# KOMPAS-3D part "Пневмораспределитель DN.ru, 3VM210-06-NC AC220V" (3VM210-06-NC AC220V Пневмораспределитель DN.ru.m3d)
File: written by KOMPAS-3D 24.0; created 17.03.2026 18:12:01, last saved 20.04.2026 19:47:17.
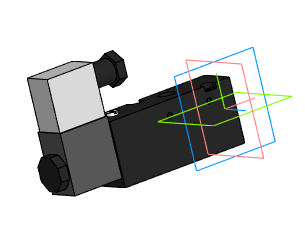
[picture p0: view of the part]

Document properties: Автор: R2D2; Полное имя файла: ..\AC24V\3VM210-06-NC AC24V Пневмораспредели тель DN.ru.cdw

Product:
- Part/product: Пневмораспределитель DN.ru  | designation 3VM210-06-NC AC220V
    Масса: 0.3
    Раздел спецификации: Прочие изделия
    Форматы листов документа: A3
    Примечание: D290-00379

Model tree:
1. Операция без истории:3

Expressions: 3VM210-06-NC AC220V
